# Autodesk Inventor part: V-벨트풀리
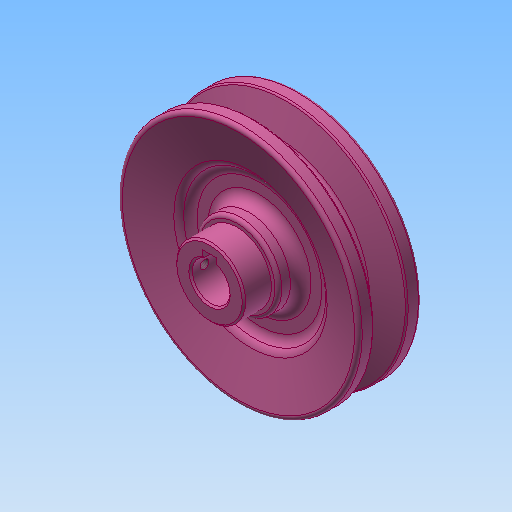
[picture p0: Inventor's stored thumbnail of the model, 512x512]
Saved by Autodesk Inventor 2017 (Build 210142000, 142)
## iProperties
Created: 2016-08
Part Number: V-벨트풀리
Material: 알루미늄 6061
Document SubType Name: Modeling
Designer: mduedu
Density: 2.71 g/cm^3
Appearance: 분홍색
Author: mduedu
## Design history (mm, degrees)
sketch "스케치1"
  geometry: L1 (0, 17.5)-(0, -9.5); L2 (10, 9.5)-(35, 9.5); L3 (35, 9.5)-(35, 4.825); L4 (35, 4.825)-(26, 2.074); L5 (26, 2.074)-(26, 0); L6 (0, 0)-(26, 0); L7 (0, -9.5)-(35, -9.5); L8 (35, -9.5)-(35, -4.825); L9 (35, -4.825)-(26, -2.074); L10 (26, -2.074)-(26, 0); L11 (32.3, 9.5)-(32.3, -9.5); L12 (10, 9.5)-(10, 17.5); L13 (10, 17.5)-(0, 17.5); 3 further points
  constraints: 26 end point, 7 point on line, 5 perpendicular, 3 symmetric about line, 2 parallel, 1 coincident, 1 horizontal alignment, 1 vertical
  dimensions: "d2" = 70 diameter of L8 L1; "d4" = 6.3 distance between parallel lines of L10 L11; "d5" = 2.7 distance between parallel lines of L11 L8; "d6" = 8 distance of point (32.3, -4) point (32.3, 4); "d7" = 34 deg angle of L9 L4; "d30" = 9.5 distance between parallel lines of L7 L6; "d32" = 27 distance between parallel lines of L13 L7; "d33" = 20 diameter of L12 L1
revolve "회전1" sketch "스케치1" stored, may be unused: angle "d8" = 90 deg
sketch "스케치2"
  geometry: L1 (-2, 0)-(2, 0); L2 (2, 0)-(2, 7.3); L3 (2, 7.3)-(-2, 7.3); L4 (-2, 7.3)-(-2, 0); C1 r 5.5 at (0, 0); 2 further points
  constraints: 8 end point, 2 coincident, 2 parallel, 1 centre point, 1 horizontal, 1 midpoint, 1 perpendicular
  dimensions: "d9" = 11 diameter of C1; "d11" = 4 distance of L2.end L3.end; "d34" = 12.8 dimension on C1 L3
extrude "돌출1" cut sketch "스케치2" stored distance "d13" = 10; taper "d14" = 0 deg
sketch "스케치3"
  geometry: L1 (35, 4.825)-(26, 2.074) reference; L2 (26, 2.074)-(26, -2.074) reference; L3 (0, 0)-(26, 0); L4 (35, 9.5)-(35, 4.825) reference; L5 (-35, 9.5)-(35, 9.5) reference; L6 (35, 9.5)-(21, 5.22); L7 (21, 5.22)-(21, 3); L8 (21, 3)-(12, 3); L9 (12, 3)-(12, 9.5); L10 (0, 9.5)-(0, -9.5); L11 (5.123, -9.5)-(-5.5, -9.5) reference; L12 (12, 9.5)-(35, 9.5)
  constraints: 14 end point, 3 midpoint, 2 parallel, 2 perpendicular, 2 point on line, 1 collinear, 1 horizontal
  dimensions: "d15" = 3 distance between parallel lines of L3 L8; "d17" = 42 diameter of L7 L10; "d18" = 24 diameter of L9 L10
revolve "회전2" sketch "스케치3" stored, may be unused: angle "d19" = 90 deg
fillet "모깎기1" dims "d20" = 0.5, "d21" = 1, "d22" = 1
fillet "모깎기2" dims "d23" = 3
fillet "모깎기3" dims "d24" = 3
fillet "모깎기4" dims "d25" = 3
chamfer "모따기1" distance "d26" = 0.5; stored, may be unused: second distance "d27" = 2, angle "d28" = 45 deg
fillet "모깎기5" dims "d29" = 1
node "작업 평면1"
sketch "스케치4"
  geometry: L1 (-9.5, 17.5)-(9.5, 17.5) reference; 2 further points
  constraints: 1 vertical alignment
  dimensions: "d41" = 4 distance from line of L1 point (0, 13.5)
hole "구멍1" sketch "스케치4" at (0, 13.5) diameter "d42" = 2.459; stored, may be unused: countersink angle "d46" = 90 deg, drill point angle "d48" = 118 deg; dims "d43" = 6, "d44" = 4, "d45" = 2, "d47" = 8
node "솔리드1"
mirror "대칭1"
